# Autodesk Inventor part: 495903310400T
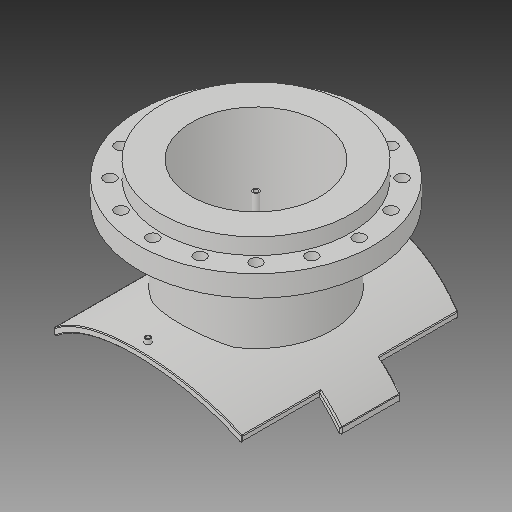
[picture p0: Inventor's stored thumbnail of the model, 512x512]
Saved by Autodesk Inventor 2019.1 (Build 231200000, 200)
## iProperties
Created: 2017-10
Part Number: 495903310400T
Material: Generic
Description: PLASSON FLANGED BRANCH SADDLE 710X400
Document SubType Name: Modeling
Designer: KIM
Mass: 2339.99 g
Surface Area: 3251.55 cm^2
Volume: 2339.99 cm^3
Density: 1 g/cm^3
Appearance: Default
Author: KIM
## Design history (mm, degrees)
derived "495904_495903.ipt"
feature "Solid1::495904_495903.ipt"
feature "Solid2::495904_495903.ipt"
tag "TaggingFeature1"
body "Solid1"
other parameters: "d1" = 15, "d2" = 477, "d4" = 0, "d6" = 152.5, "d7" = 0, "d11" = 3.55, "d12" = 380.6, "d13" = 14, "d14" = 274.5, "d16" = 5 deg, "d18" = 4, "d19" = 14, "d20" = 0, "d21" = 3, "d22" = 0, "d36" = 274.5, "d38" = 0, "d39" = 2, "d41" = 327, "d42" = 482, "d43" = 595, "d44" = 224, "d46" = 385.6, "d47" = 16, "d48" = 10.4, "d49" = 196, "d51" = 724.2, "d53" = 0, "d55" = 262.5, "d57" = 0, "d59" = 360 deg, "d61" = 54, "d63" = 0, "d_1" = 482, "x_" = 15, "D_" = 16, "DN_" = 327, "D_1" = 595, "t_" = 54, "Dp_" = 525
